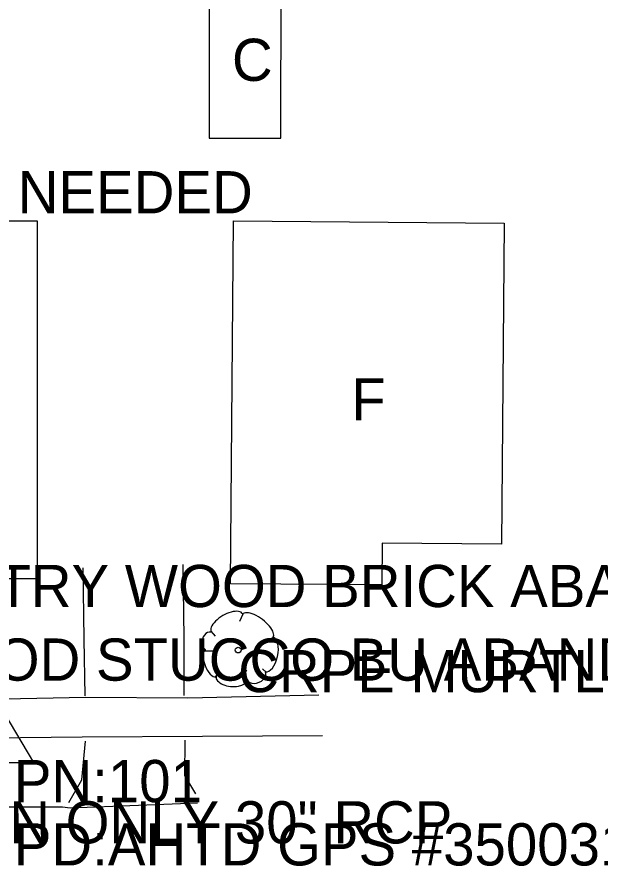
# Model space of a CAD drawing. Extents: x 1304270 to 1306561, y 1876019 to 1876752.
# Drawn here: x 1306320 to 1306389.1, y 1876425.8 to 1876526.4 of the extents above; entities that cross this region are included whole.
import ezdxf

# ---------------------------------------------------------------- set-up
doc = ezdxf.new("R2010")
doc.units = 0
for name, color, linetype in [('S_BUILDING', 7, 'Continuous'), ('S_BUILDING_ANNOT', 7, 'Continuous'), ('S_DRIVEWAY', 7, 'Continuous'), ('S_EDGE_PAVEMENT', 7, 'Continuous'), ('S_PRIMARY_CTL', 7, 'Continuous'), ('S_PRIMARY_CTL_ANNOT', 7, 'Continuous'), ('S_SANITARY_SEWER_ANNOT', 7, 'Continuous'), ('S_SIDEWALK', 7, 'Continuous'), ('S_STORM_SEWER_ANNOT', 7, 'Continuous'), ('S_SURVEY_TEXT_ANNOT', 7, 'Continuous'), ('S_TREE', 7, 'Continuous'), ('S_TREE_ANNOT', 7, 'Continuous')]:
    doc.layers.add(name, color=color, linetype=linetype)

msp = doc.modelspace()

# ---------------------------------------------------------------- linework, layer by layer
at = {"layer": 'S_BUILDING'}
for points in [[(1306342.76, 1876530.65), (1306342.73, 1876512.09), (1306351.24, 1876512.07), (1306351.28, 1876530.63)], [(1306290.94, 1876517.15), (1306290.95, 1876463.4), (1306303.75, 1876463.4), (1306303.75, 1876459.89), (1306322.39, 1876459.89), (1306322.38, 1876502.24), (1306307.58, 1876502.24), (1306307.58, 1876517.16)], [(1306345.27, 1876459.27), (1306345.63, 1876502.29), (1306377.74, 1876502.02), (1306377.42, 1876463.96), (1306363.26, 1876464.08), (1306363.22, 1876459.12)]]:
    msp.add_lwpolyline(points, close=True, dxfattribs=at)
at = {"layer": 'S_DRIVEWAY'}
for points in [[(1306327.77, 1876461.14), (1306327.89, 1876452.71), (1306328, 1876445.99)], [(1306339.77, 1876446.04), (1306339.79, 1876452.82), (1306339.68, 1876461.55)], [(1306326.1, 1876433.36), (1306327.66, 1876436.01), (1306328.1, 1876440.6)], [(1306339.85, 1876440.72), (1306339.83, 1876436.53), (1306341.11, 1876434.36)]]:
    msp.add_lwpolyline(points, dxfattribs=at)
at = {"layer": 'S_EDGE_PAVEMENT'}
msp.add_lwpolyline([(1306113.12, 1876430.25), (1306126.16, 1876430.64), (1306148.96, 1876430.86), (1306171.76, 1876431.08), (1306196.43, 1876430.92), (1306201.22, 1876431.25), (1306201.59, 1876430.5), (1306204.64, 1876430.62), (1306209.26, 1876430.77), (1306212.62, 1876431.11), (1306218.85, 1876431.26), (1306235.37, 1876431.61), (1306256.72, 1876432.09), (1306262.37, 1876432.42), (1306275.55, 1876432.51), (1306288.74, 1876432.59), (1306294.65, 1876432.63), (1306294.99, 1876432.68), (1306300.36, 1876432.78), (1306312.86, 1876432.81), (1306325.37, 1876432.84), (1306326.28, 1876432.72), (1306334.35, 1876433.02), (1306341.35, 1876433.31)], dxfattribs=at)
at = {"layer": 'S_PRIMARY_CTL'}
for p in [(1306312.09, 1876454.58), (1306302.06, 1876438.07)]:
    msp.add_line(p, (1306321.91, 1876438.07), dxfattribs=at)
at = {"layer": 'S_SIDEWALK'}
for points in [[(1306307, 1876445.78), (1306316.52, 1876445.6), (1306328.09, 1876445.83), (1306340.2, 1876445.76), (1306355.77, 1876446.1)], [(1306258.08, 1876440.25), (1306262.7, 1876440.41), (1306268.2, 1876440.45), (1306279.65, 1876440.65), (1306293.39, 1876440.9), (1306307.14, 1876441.15), (1306316.67, 1876441.01), (1306327.71, 1876441.13), (1306341.95, 1876441.2), (1306356.19, 1876441.27)]]:
    msp.add_lwpolyline(points, dxfattribs=at)
at = {"layer": 'S_TREE'}
for p, q in [((1306346.75, 1876455.66), (1306346.36, 1876454.8)), ((1306342.95, 1876453.64), (1306343.46, 1876453.06)), ((1306350.31, 1876452.87), (1306349.66, 1876452.6)), ((1306342.29, 1876451.32), (1306343.42, 1876451.32)), ((1306343.46, 1876448.14), (1306343.92, 1876448.84)), ((1306349.54, 1876448.76), (1306349.07, 1876449.19)), ((1306347.14, 1876447.87), (1306347.06, 1876448.64))]:
    msp.add_line(p, q, dxfattribs=at)
msp.add_circle((1306346.19, 1876451.41), 0.341, dxfattribs=at)
for centre, major_axis, ratio, start_param, end_param in [((1306344.86, 1876454.61), (1.86, 1.08), 0.471018, 0, 3.141593), ((1306348.51, 1876454.29), (-1.81, 1.36), 0.405113, 3.141593, 6.283186), ((1306342.62, 1876452.5), (0.31, 1.03), 0.646762, 0, 3.141593), ((1306349.87, 1876450.88), (0.46, 2.04), 0.482994, 3.141593, 6.283185), ((1306342.93, 1876449.85), (-0.61, 1.6), 0.420543, 6.283185, 9.424777), ((1306348.34, 1876448.36), (1.09, 0.46), 0.711534, 3.141592, 6.283185), ((1306345.39, 1876448.07), (-1.83, 0.19), 0.529943, 0, 3.141593)]:
    msp.add_ellipse(centre, major_axis=major_axis, ratio=ratio, start_param=start_param, end_param=end_param, dxfattribs=at)

# ---------------------------------------------------------------- texts
at = {"layer": 'S_BUILDING_ANNOT'}
for s, p in [('C', (1306345.45, 1876518.86)), ('F', (1306359.6, 1876478.62)), ('1STRY WOOD BRICK ABANDON', (1306309.34, 1876456.5))]:
    msp.add_text(s, height=5, dxfattribs=at).set_placement(p)
at = {"layer": 'S_PRIMARY_CTL_ANNOT'}
for s, p in [('PN:101', (1306319.59, 1876433.38)), ('PD:AHTD GPS #350031A', (1306319.59, 1876425.88))]:
    msp.add_text(s, height=5, dxfattribs=at).set_placement(p)
at = {"layer": 'S_SANITARY_SEWER_ANNOT'}
msp.add_text('OD BACK/ADD FG IF NEEDED', height=5, dxfattribs=at).set_placement((1306253.18, 1876503.17))
at = {"layer": 'S_STORM_SEWER_ANNOT'}
msp.add_text('DIRECTION ONLY 30" RCP', height=5, dxfattribs=at).set_placement((1306287.1, 1876428.49))
at = {"layer": 'S_SURVEY_TEXT_ANNOT'}
msp.add_text('1STORY WOOD STUCCO BU ABANDONED BU', height=5, dxfattribs=at).set_placement((1306277.32, 1876447.78))
at = {"layer": 'S_TREE_ANNOT'}
msp.add_text('CRPE MURTLE', height=5, dxfattribs=at).set_placement((1306346.19, 1876446.41))

doc.saveas('drawing.dxf')
